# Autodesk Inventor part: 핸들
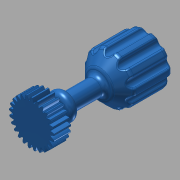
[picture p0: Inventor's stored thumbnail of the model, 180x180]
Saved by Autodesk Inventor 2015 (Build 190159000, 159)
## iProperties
Created: 2017-04
Part Number: 핸들
Material: 강철, 연강
Document SubType Name: Modeling
Designer: mduedu
Categories: <?xml version="1.0" encoding="UTF-16"?> <MemberInstance><Categories><FamilyTemplate><FamilyTemplateParameter ValueType="xs:double" Id="1" ObjectReferenceKey="da
Density: 7.86 g/cm^3
Appearance: 청록색
Mass: 193.541 g
Surface Area: 74.5322 cm^2
Volume: 24.6236 cm^3
CustomPartVersion: 1
Author: mduedu
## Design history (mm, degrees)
sketch "Sketch1"
  geometry: C1 r 13.5 at (0, 0)
  constraints: 1 centre point
  dimensions: "d0" = 27 diameter of C1 (= da_da)
extrude "Extrusion1" new body sketch "Sketch1" distance "d1" = 10 (= da_b); taper "d2" = 0 deg
workplane "Work Plane2"
sketch "Sketch2"
  geometry: C1 r 13.5 at (0, 0) reference; C2 r 12.5 at (0, 0)
  constraints: 1 centre point, 1 coincident
  dimensions: "d3" = 25 diameter of C2 (= da_dw)
feature "피치 지름" sketch "Sketch2" dims "d4" = 10, "d5" = 0
workplane "Work Plane8"
workplane "Work Plane9"
feature "스퍼 기어" dims "da_b" = 10, "da_d" = 25, "da_aw" = 25, "da_da" = 27, "da_df" = 22.5, "da_dw" = 25, angle "da_beta" = 0 deg, "da_lefttooth" = 0, "da_righttooth" = 0
sketch "스케치3"
  geometry: C1 r 5 at (0, 0); 1 further point
  constraints: 1 centre point, 1 coincident
  dimensions: "d49" = 10 diameter of C1
extrude "돌출2" join sketch "스케치3" distance "d50" = 60; taper "d51" = 0 deg
sketch "스케치4"
  geometry: C1 r 15 at (0, 0); 1 further point
  constraints: 1 centre point, 1 coincident
  dimensions: "d52" = 30 diameter of C1
extrude "돌출3" join sketch "스케치4" distance "d53" = 30; taper "d54" = 0 deg
chamfer "모따기1" distance "d55" = 7; stored, may be unused: second distance "d56" = 2, angle "d57" = 45 deg
sketch "스케치5"
  geometry: L1 (0, 2.2)-(0, -13.2) reference; L2 (0, -5)-(8, -5); L3 (8, -5)-(8, -11); L4 (8, -11)-(0, -11); L5 (0, -11)-(0, -5); 1 further point
  constraints: 8 end point, 2 parallel, 1 horizontal, 1 perpendicular, 1 point on line
  dimensions: "d58" = 5 distance from line of L2 point (0, 0); "d59" = 6 distance of L2.end L3.end; "d60" = 16 diameter of L3 L1
revolve "회전1" sketch "스케치5" stored, may be unused: angle "d61" = 90 deg
fillet "모깎기1" dims "d62" = 3
fillet "모깎기2" dims "d65" = 3
fillet "모깎기3" dims "d72" = 3
sketch "스케치6"
  geometry: C1 r 2.5 at (0, 15); 2 further points
  constraints: 2 vertical alignment, 1 centre point, 1 other
  dimensions: "d66" = 5 diameter of C1
extrude "돌출4" cut sketch "스케치6" stored distance "d67" = 35; taper "d68" = 0 deg
fillet "모깎기4" dims "d73" = 1
body "Solid1"
pattern_circular "원형 패턴2" dims angle "d75" = 360 deg
body "Srf1"
other parameters: "d16" = 25 (= da_aw), "d17" = 0, "d34" = 1.25664 (computed from da_z), "d39" = 0, "d41" = 0, "d43" = 25 (= da_aw), "d46" = 25 (= da_aw), "d47" = 0, "d48" = 0
